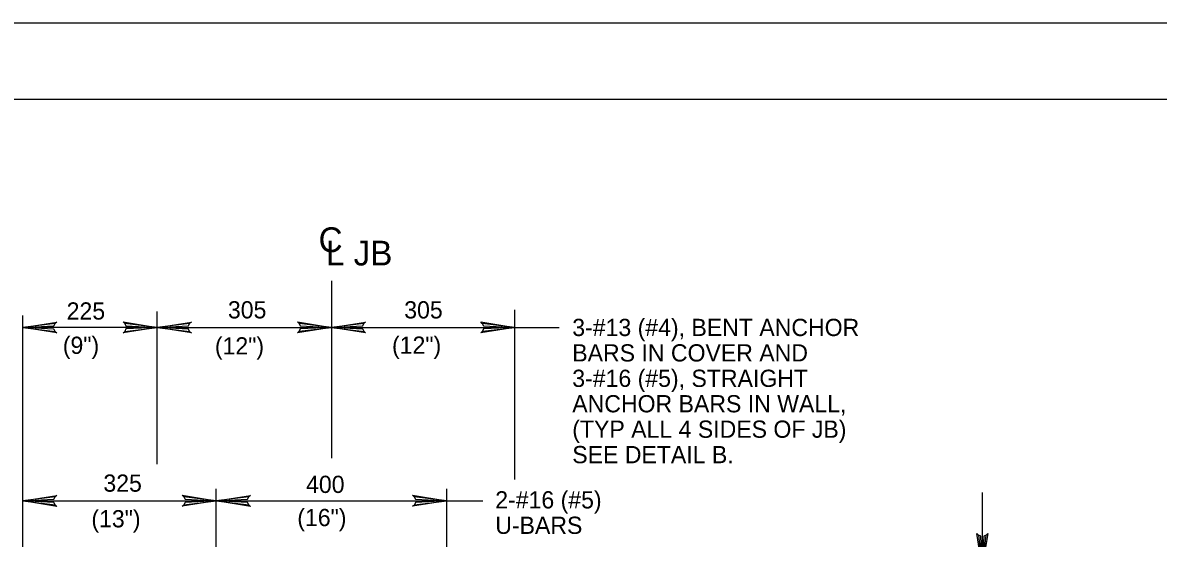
# Model space of a CAD drawing. Extents: x 638455 to 640199, y 298558 to 299152.
# Drawn here: x 638610.5 to 638831.8, y 299051.7 to 299152.2 of the extents above; entities that cross this region are included whole.
import ezdxf

# ---------------------------------------------------------------- set-up
doc = ezdxf.new("R2010")
doc.units = 0
for name, color, linetype in [('1', 7, 'Continuous'), ('2', 7, 'Continuous'), ('3', 7, 'Continuous'), ('PLT-BNDY', 7, 'Continuous')]:
    doc.layers.add(name, color=color, linetype=linetype)

msp = doc.modelspace()

# ---------------------------------------------------------------- linework, layer by layer
at = {"layer": '1'}
msp.add_lwpolyline([(639279.61, 298573.25), (639279.61, 299137.25), (638493.61, 299137.25), (638493.61, 298573.25), (639279.61, 298573.25), (639279.61, 298599.61), (639079.61, 298599.61), (639079.61, 298664.29), (639279.61, 298664.29), (639279.61, 298693.25), (639079.61, 298693.25), (639079.61, 298573.25), (639158.42, 298573.25), (639158.42, 298599.61), (639158.42, 298573.25), (639235.42, 298573.25), (639235.42, 298599.61), (639235.42, 298587.29), (639279.61, 298587.29)], dxfattribs=at)
at = {"layer": '2'}
for p, q in [((638670.65, 299101.94), (638670.65, 299087.3)), ((638636.67, 299066.18), (638636.67, 299095.91)), ((638706.37, 299063.18), (638706.37, 299096.25)), ((638610.47, 299048.49), (638610.47, 299095.17)), ((638636.67, 299092.82), (638610.47, 299092.82)), ((638636.67, 299092.82), (638670.65, 299092.82)), ((638670.65, 299092.82), (638706.37, 299092.82)), ((638706.37, 299092.82), (638715.03, 299092.82)), ((638670.65, 299090.75), (638670.65, 299067.31)), ((638648.2, 299044.35), (638648.2, 299061.35)), ((638693.1, 299044.59), (638693.1, 299061.35)), ((638797.47, 299060.64), (638797.47, 299046)), ((638610.47, 299059), (638648.2, 299059)), ((638648.2, 299059), (638670.65, 299059)), ((638670.65, 299059), (638693.1, 299059)), ((638693.1, 299059), (638700.12, 299059))]:
    msp.add_line(p, q, dxfattribs=at)
for points in [[(638616.8, 299092.03), (638616.56, 299092.48), (638610.47, 299092.82), (638616.8, 299092.03), (638617.12, 299091.75), (638610.47, 299092.82), (638616.55, 299093.12), (638616.78, 299093.57), (638610.47, 299092.82), (638617.12, 299093.88), (638616.78, 299093.57)], [(638630.34, 299093.62), (638630.58, 299093.16), (638636.67, 299092.82), (638630.34, 299093.62), (638630.02, 299093.89), (638636.67, 299092.82), (638630.58, 299092.52), (638630.36, 299092.06), (638636.67, 299092.82), (638630.02, 299091.76), (638630.36, 299092.06)], [(638643, 299092.03), (638642.76, 299092.48), (638636.67, 299092.82), (638643, 299092.03), (638643.33, 299091.75), (638636.67, 299092.82), (638642.76, 299093.12), (638642.98, 299093.58), (638636.67, 299092.82), (638643.33, 299093.88), (638642.98, 299093.58)], [(638664.32, 299093.62), (638664.56, 299093.16), (638670.65, 299092.82), (638664.32, 299093.62), (638664, 299093.89), (638670.65, 299092.82), (638664.56, 299092.52), (638664.34, 299092.07), (638670.65, 299092.82), (638664, 299091.76), (638664.34, 299092.07)], [(638676.98, 299092.03), (638676.74, 299092.48), (638670.65, 299092.82), (638676.98, 299092.03), (638677.3, 299091.75), (638670.65, 299092.82), (638676.74, 299093.12), (638676.96, 299093.58), (638670.65, 299092.82), (638677.3, 299093.88), (638676.96, 299093.58)], [(638700.04, 299093.62), (638700.28, 299093.16), (638706.37, 299092.82), (638700.04, 299093.62), (638699.72, 299093.89), (638706.37, 299092.82), (638700.28, 299092.52), (638700.06, 299092.07), (638706.37, 299092.82), (638699.72, 299091.76), (638700.06, 299092.07)], [(638616.8, 299058.21), (638616.56, 299058.67), (638610.47, 299059), (638616.8, 299058.21), (638617.12, 299057.93), (638610.47, 299059), (638616.55, 299059.31), (638616.78, 299059.76), (638610.47, 299059), (638617.12, 299060.06), (638616.78, 299059.76)], [(638641.87, 299059.8), (638642.11, 299059.34), (638648.2, 299059), (638641.87, 299059.8), (638641.55, 299060.08), (638648.2, 299059), (638642.11, 299058.71), (638641.89, 299058.25), (638648.2, 299059), (638641.55, 299057.95), (638641.89, 299058.25)], [(638654.53, 299058.21), (638654.29, 299058.67), (638648.2, 299059), (638654.53, 299058.21), (638654.85, 299057.93), (638648.2, 299059), (638654.29, 299059.31), (638654.51, 299059.76), (638648.2, 299059), (638654.85, 299060.06), (638654.51, 299059.76)], [(638686.77, 299059.8), (638687, 299059.34), (638693.1, 299059), (638686.77, 299059.8), (638686.44, 299060.08), (638693.1, 299059), (638687.01, 299058.71), (638686.79, 299058.25), (638693.1, 299059), (638686.44, 299057.95), (638686.79, 299058.25)], [(638798.26, 299052.33), (638797.81, 299052.09), (638797.47, 299046), (638798.26, 299052.33), (638798.54, 299052.65), (638797.47, 299046), (638797.17, 299052.09), (638796.71, 299052.31), (638797.47, 299046), (638796.41, 299052.65), (638796.71, 299052.31)]]:
    msp.add_lwpolyline(points, dxfattribs=at)
at = {"layer": 'PLT-BNDY'}
msp.add_lwpolyline([(638454.61, 299152.25), (639295.61, 299152.25), (639295.61, 298558.25), (638454.61, 298558.25)], close=True, dxfattribs=at)

# ---------------------------------------------------------------- texts
at = {"layer": '1'}
for s, p in [('(12")', (638647.92, 299087.55)), ('(12")', (638682.44, 299087.69)), ('(13")', (638623.85, 299053.83)), ('(16")', (638663.98, 299054.07))]:
    msp.add_text(s, height=3.36, dxfattribs=at).set_placement(p)
at = {"layer": '3'}
for s, height, p in [('C', 4.84, (638668.13, 299107.5)), ('L JB', 4.838, (638669.57, 299104.9)), ('225', 3.36, (638619.03, 299094.35)), ('305', 3.36, (638650.46, 299094.58)), ('305', 3.36, (638684.82, 299094.57)), ('3-#13 (#4), BENT ANCHOR', 3.36, (638717.57, 299091.14)), ('(9")', 3.36, (638618.28, 299087.66)), ('BARS IN COVER AND', 3.36, (638717.57, 299086.18)), ('3-#16 (#5), STRAIGHT', 3.36, (638717.57, 299081.22)), ('ANCHOR BARS IN WALL,', 3.36, (638717.57, 299076.26)), ('(TYP ALL 4 SIDES OF JB)', 3.36, (638717.57, 299071.3)), ('SEE DETAIL B.', 3.36, (638717.57, 299066.34)), ('325', 3.36, (638626.19, 299060.78)), ('400', 3.36, (638665.69, 299060.54)), ('2-#16 (#5)', 3.36, (638702.56, 299057.52)), ('U-BARS', 3.36, (638702.56, 299052.56))]:
    msp.add_text(s, height=height, dxfattribs=at).set_placement(p)

doc.saveas('drawing.dxf')
